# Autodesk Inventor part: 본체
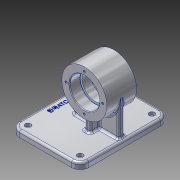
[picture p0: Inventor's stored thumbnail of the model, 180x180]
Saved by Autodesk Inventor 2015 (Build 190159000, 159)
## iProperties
Created: 2019-09
Part Number: 본체
Material: 알루미늄 6061
Document SubType Name: Modeling
Designer: Lineart
Density: 2.7 g/cm^3
Appearance: 알루미늄 - 평지
Mass: 554.606 g
Surface Area: 496.225 cm^2
Volume: 205.41 cm^3
Author: Lineart
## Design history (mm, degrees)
sketch "스케치1"
  geometry: L1 (-51, -49)-(51, -49); L2 (63, -37)-(63, 37); L3 (51, 49)-(-51, 49); L4 (-63, 37)-(-63, -37); L5 (-63, -49)-(63, 49); L6 (63, -49)-(-63, 49); A1 r 12 centre (-51, 37) between (-51, 49) and (-63, 37); A2 r 12 centre (51, 37) between (63, 37) and (51, 49); A3 r 12 centre (51, -37) between (51, -49) and (63, -37); A4 r 12 centre (-51, -37) between (-63, -37) and (-51, -49); 1 further point
  constraints: 12 end point, 8 point on circle, 8 point on line, 8 tangent, 4 centre point, 3 equal radius, 2 midpoint, 2 parallel, 1 horizontal, 1 perpendicular
  dimensions: "d0" = 126 distance of L6.end L5.end; "d1" = 98 distance of L5.end L6.start; "d2" = 12 radius of A1
extrude "돌출1" new body sketch "스케치1" distance "d3" = 9; taper "d4" = 0 deg
sketch "스케치2"
  geometry: A1 r 12 centre (-51, 37) between (-51, 49) and (-63, 37) reference; A2 r 12 centre (51, 37) between (63, 37) and (51, 49) reference; A3 r 12 centre (-51, -37) between (-63, -37) and (-51, -49) reference; A4 r 12 centre (51, -37) between (51, -49) and (63, -37) reference; 5 further points
  constraints: 4 coincident
hole "구멍1" sketch "스케치2" at (-51, 37), (51, 37), (-51, -37), (51, -37) diameter "d5" = 4.5; stored, may be unused: countersink angle "d9" = 90 deg, drill point angle "d11" = 0 deg; dims "d6" = 6, "d7" = 8, "d8" = 4.4, "d10" = 9
sketch "스케치3"
  geometry: L1 (-17, -9)-(17, -9); L2 (17, -9)-(17, -17); L3 (17, -17)-(-17, -17); L4 (-17, -17)-(-17, -9); L5 (17, -13)-(-17, -13); L6 (51, 49)-(-51, 49) reference; L7 (-4, 19)-(4, 19); L8 (4, 19)-(4, -45); L9 (4, -45)-(-4, -45); L10 (-4, -45)-(-4, 19); 5 further points
  constraints: 18 end point, 6 midpoint, 4 parallel, 2 horizontal, 2 perpendicular, 2 vertical alignment, 1 horizontal alignment
  dimensions: "d14" = 34 distance of L2.end L3.end; "d15" = 8 distance of L1.end L2.end; "d16" = 62 distance between parallel lines of L5 L6; "d19" = 8 distance of L8.end L9.end; "d20" = 64 distance of L7.end L8.end
extrude "돌출3" join sketch "스케치3" distance "d21" = 50; taper "d22" = 0 deg
sketch "스케치4"
  geometry: L1 (-9, 59)-(-17, 59) reference; L2 (-34.75, 0)-(-39.25, 0) reference; C1 r 32 at (-13, 59); 2 further points
  constraints: 1 centre point, 1 coincident, 1 midpoint
  dimensions: "d23" = 64 diameter of C1; "d24" = 59 distance from line of L2 C1.centre
extrude "돌출4" join sketch "스케치4" stored distance "d25" = 42; taper "d26" = 0 deg
sketch "스케치5"
  geometry: C1 r 32 at (0, 0) reference; C2 r 21 at (0, 0); 1 further point
  constraints: 1 centre point, 1 coincident
  dimensions: "d27" = 42 diameter of C2
extrude "돌출5" cut sketch "스케치5" distance "d28" = 15; taper "d29" = 0 deg
sketch "스케치6"
  geometry: C1 r 21 at (0, 0) reference; C2 r 18 at (0, 0); 1 further point
  constraints: 1 centre point, 1 coincident
  dimensions: "d30" = 36 diameter of C2
extrude "돌출6" cut sketch "스케치6" distance "d31" = 12; taper "d32" = 0 deg
sketch "스케치7"
  geometry: C1 r 32 at (0, 0) reference; C2 r 21 at (0, 0); 1 further point
  constraints: 1 centre point, 1 coincident
  dimensions: "d33" = 42 diameter of C2
extrude "돌출7" cut sketch "스케치7" distance "d34" = 15; taper "d35" = 0 deg
sketch "스케치8"
  geometry: C1 r 21 at (0, 0) reference; 2 further points
  constraints: 1 horizontal alignment
  dimensions: "d36" = 26 distance of C1.centre point (-26, 0)
hole "구멍2" sketch "스케치8" at (-26, 0) diameter "d37" = 3.242; stored, may be unused: countersink angle "d41" = 90 deg, drill point angle "d43" = 118 deg; dims "d38" = 8, "d39" = 8, "d40" = 4.4, "d42" = 10
fillet "모깎기1" dims "d47" = 3
fillet "모깎기2" dims "d48" = 3
fillet "모깎기3" dims "d49" = 3
chamfer "모따기1" distance "d50" = 1; stored, may be unused: second distance "d51" = 2, angle "d52" = 45 deg
sketch "스케치9"
  geometry: L1 (51, 49)-(-51, 49) reference; L2 (63, -37)-(63, 37) reference; 2 further points
  constraints: 1 other
  dimensions: "d53" = 10 distance from line of point (0, 39) L1; "d54" = 63 distance from line of L2 point (0, 39)
feature "엠보싱1" sketch "스케치9" dims "d55" = 0.5, "d56" = 0
fillet "모깎기4" dims "d57" = 0.3
node "솔리드1"
pattern_circular "원형 패턴1" dims angle "d45" = 360 deg
mirror "대칭1"
